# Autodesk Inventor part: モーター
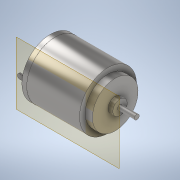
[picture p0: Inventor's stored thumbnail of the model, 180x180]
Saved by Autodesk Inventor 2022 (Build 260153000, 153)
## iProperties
Created: 2024-10
Part Number: モーター
Material: 鋼、鋳鋼
Document SubType Name: Modeling
Designer: jsat7
Density: 7.85 g/cm^3
Appearance: 半つや出し
Author: jsat7
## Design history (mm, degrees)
sketch "スケッチ1"
  geometry: 1 further point
sketch "スケッチ2"
  geometry: L1 (0, 0)-(27, 0); L2 (27, 0)-(27, 3); L3 (27, 3)-(25, 3); L4 (25, 3)-(25, 9.5); L5 (25, 9.5)-(22, 9.5); L6 (22, 9.5)-(22, 11.85); L7 (22, 11.85)-(0, 11.85); L8 (0, 11.85)-(0, 0)
  constraints: 16 end point, 7 perpendicular, 1 horizontal
  dimensions: "d0" = 22 distance of L6.end L7.end; "d1" = 25 distance from line of L8 L4.end; "d2" = 3 distance between parallel lines of L1 L3; "d3" = 9.5 distance from line of L1 L4.end; "d4" = 11.85 distance between parallel lines of L1 L7; "d5" = 2 distance of L2.end L3.end
revolve "回転1" sketch "スケッチ2" stored, may be unused: angle "d6" = 90 deg
sketch "スケッチ3"
  geometry: L1 (0, 0)-(-4, 0); L2 (-4, 0)-(-4, 4.25); L3 (-4, 4.25)-(-2, 4.25); L4 (-2, 4.25)-(-2, 11.85); L5 (0, -11.85)-(0, 11.85) reference; L6 (-2, 11.85)-(0, 11.85); L7 (0, 11.85)-(0, 0)
  constraints: 12 end point, 5 perpendicular, 1 horizontal
  dimensions: "d7" = 2 distance of L2.end L3.end; "d8" = 2 distance of L4.end L5.end; "d9" = 4.25 distance of L1.end L2.end
revolve "回転2" sketch "スケッチ3" stored, may be unused: angle "d10" = 90 deg
sketch "スケッチ4"
  geometry: C1 r 1 at (0, 0); 1 further point
  constraints: 1 centre point, 1 coincident
  dimensions: "d11" = 2 diameter of C1
extrude "押し出し1" join sketch "スケッチ4" distance "d12" = 7; taper "d13" = 0 deg
sketch "スケッチ5"
  geometry: C1 r 1 at (0, 0) reference; C2 r 1 at (0, 0); 1 further point
  constraints: 1 centre point, 1 coincident
  dimensions: "d14" = 2 diameter of C2
extrude "押し出し2" join sketch "スケッチ5" distance "d15" = 1; taper "d16" = 0 deg
sketch "スケッチ6"
  geometry: 1 further point
node "作業平面1"
sketch "スケッチ7"
  geometry: L1 (-2, -4.25)-(-2, 4.25) reference; L2 (-2, 0)-(-3.732, 0); L3 (-2, 1)-(-5, 1); L4 (-2, -1)-(-5, -1); L5 (-5, 1)-(-5, -1) reference; A1 r 1 centre (-4.992, 0) between (-5, 1) and (-5, -1); 1 further point
  constraints: 6 end point, 3 horizontal, 2 point on circle, 2 point on line, 1 centre point, 1 midpoint, 1 other
  dimensions: "d18" = 2 distance between parallel lines of L4 L3; "d19" = 3 distance of L3.start L3.end; "d20" = 3 distance of L4.start L4.end
extrude "押し出し3" join sketch "スケッチ7" distance "d22" = 0.5; taper "d23" = 0 deg
mirror "ミラー1"
node "ソリッド1"
node "ソリッド2"
other parameters: "d17" = 9.25, "d21" = 0.5
